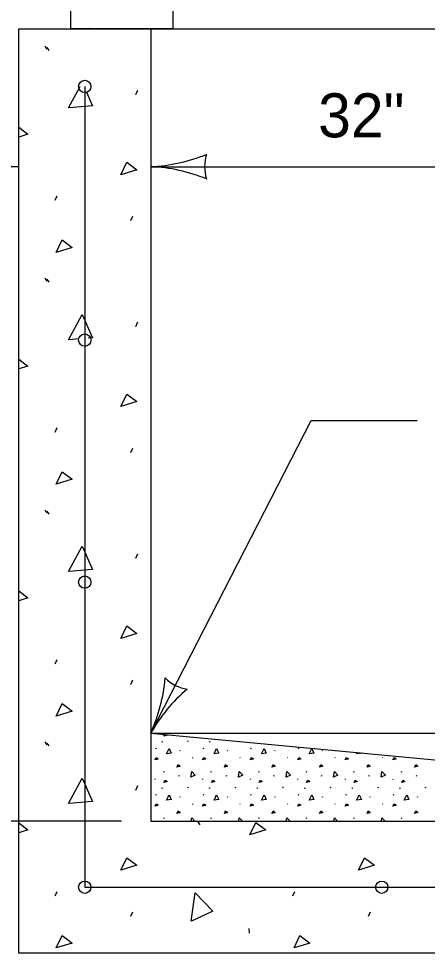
# Model space of a CAD drawing. Extents: x 49991.4 to 50041.6, y 49987.6 to 50011.4.
# Drawn here: x 50038.338 to 50038.895, y 49992.177 to 49993.451 of the extents above; entities that cross this region are included whole.
import ezdxf

# ---------------------------------------------------------------- set-up
doc = ezdxf.new("R2010")
doc.units = 0
for name, color, linetype in [('Level 1', 7, 'Continuous'), ('Level 2', 7, 'Continuous'), ('Level 3', 7, 'Continuous'), ('Level 4', 7, 'Continuous')]:
    doc.layers.add(name, color=color, linetype=linetype)

msp = doc.modelspace()

# ---------------------------------------------------------------- linework, layer by layer
at = {"layer": 'Level 1'}
for p, q in [((50038.3736, 49993.4132), (50038.3763, 49993.4092)), ((50038.3763, 49993.4117), (50038.379, 49993.4076)), ((50038.4974, 49993.3475), (50038.5001, 49993.3536)), ((50038.3878, 49993.2034), (50038.3905, 49993.2095)), ((50038.4906, 49993.1756), (50038.4933, 49993.1817)), ((50038.3736, 49993.0971), (50038.3763, 49993.0931)), ((50038.3763, 49993.0956), (50038.379, 49993.0915)), ((50038.4974, 49993.0314), (50038.5001, 49993.0375)), ((50038.3878, 49992.8873), (50038.3905, 49992.8934)), ((50038.4906, 49992.8595), (50038.4933, 49992.8656)), ((50038.3736, 49992.781), (50038.3763, 49992.777)), ((50038.3763, 49992.7795), (50038.379, 49992.7754)), ((50038.4974, 49992.7153), (50038.5001, 49992.7214)), ((50038.3878, 49992.5712), (50038.3905, 49992.5773)), ((50038.4906, 49992.5434), (50038.4933, 49992.5495)), ((50038.5179, 49992.4768), (50039.4779, 49992.3868)), ((50038.3736, 49992.465), (50038.3763, 49992.4609)), ((50038.3763, 49992.4634), (50038.379, 49992.4594)), ((50038.4974, 49992.3992), (50038.5001, 49992.4053)), ((50038.582, 49992.3559), (50038.5847, 49992.3519)), ((50038.3878, 49992.2551), (50038.3905, 49992.2612)), ((50038.7119, 49992.2551), (50038.7146, 49992.2612)), ((50038.4906, 49992.2274), (50038.4933, 49992.2335)), ((50038.8148, 49992.2274), (50038.8175, 49992.2335)), ((50038.6515, 49992.2104), (50038.6522, 49992.2043))]:
    msp.add_line(p, q, dxfattribs=at)
msp.add_lwpolyline([(50038.4091, 49993.4368), (50038.4091, 49993.6168), (50038.5479, 49993.6168), (50038.5479, 49993.4368)], close=True, dxfattribs=at)
for points in [[(50039.6579, 49992.3552), (50039.6579, 49992.1768), (50038.3379, 49992.1768), (50038.3379, 49993.4368), (50039.6579, 49993.4368), (50039.6579, 49992.5964)], [(50038.432, 49993.4368), (50038.4326, 49993.438), (50038.4342, 49993.4368)], [(50038.5179, 49993.4368), (50038.5179, 49992.3568), (50039.4779, 49992.3568), (50039.4779, 49993.4368)], [(50038.406, 49993.3292), (50038.4215, 49993.3584)], [(50038.4279, 49993.3585), (50038.4279, 49992.2668), (50039.5679, 49992.2668), (50039.5679, 49992.3563)], [(50038.4297, 49993.3516), (50038.4385, 49993.3319), (50038.4067, 49993.3292)], [(50038.3379, 49993.3029), (50038.3505, 49993.2934), (50038.3379, 49993.2894)], [(50038.4772, 49993.2382), (50038.4853, 49993.2551), (50038.4989, 49993.245), (50038.4772, 49993.2382)], [(50038.3891, 49993.1323), (50038.3972, 49993.1492), (50038.4108, 49993.1391), (50038.3891, 49993.1323)], [(50038.406, 49993.0131), (50038.4243, 49993.0477), (50038.4385, 49993.0159), (50038.4325, 49993.0153)], [(50038.4202, 49993.0143), (50038.4067, 49993.0131)], [(50038.3379, 49992.9868), (50038.3505, 49992.9773), (50038.3379, 49992.9733)], [(50038.4772, 49992.9221), (50038.4853, 49992.9391), (50038.4989, 49992.9289), (50038.4772, 49992.9221)], [(50038.3891, 49992.8162), (50038.3972, 49992.8331), (50038.4108, 49992.823), (50038.3891, 49992.8162)], [(50038.406, 49992.6971), (50038.4243, 49992.7316), (50038.4385, 49992.6998), (50038.4067, 49992.6971)], [(50038.3379, 49992.6707), (50038.3505, 49992.6612), (50038.3379, 49992.6572)], [(50038.4772, 49992.6061), (50038.4853, 49992.623), (50038.4989, 49992.6128), (50038.4772, 49992.6061)], [(50038.3891, 49992.5001), (50038.3972, 49992.5171), (50038.4108, 49992.5069), (50038.3891, 49992.5001)], [(50038.406, 49992.381), (50038.4243, 49992.4155), (50038.4385, 49992.3837), (50038.4067, 49992.381)], [(50038.3379, 49992.3546), (50038.3505, 49992.3451), (50038.3379, 49992.3411)], [(50038.653, 49992.3383), (50038.6611, 49992.3553), (50038.6747, 49992.3451), (50038.653, 49992.3383)], [(50038.4772, 49992.29), (50038.4853, 49992.3069), (50038.4989, 49992.2967), (50038.4772, 49992.29)], [(50038.8014, 49992.29), (50038.8095, 49992.3069), (50038.823, 49992.2967), (50038.8014, 49992.29)], [(50038.5729, 49992.2204), (50038.5783, 49992.259), (50038.6025, 49992.234), (50038.5736, 49992.2206)], [(50038.3891, 49992.1841), (50038.3972, 49992.201), (50038.4108, 49992.1908), (50038.3891, 49992.1841)], [(50038.7133, 49992.1841), (50038.7214, 49992.201), (50038.7349, 49992.1908), (50038.7133, 49992.1841)]]:
    msp.add_lwpolyline(points, dxfattribs=at)
for centre in [(50038.4279, 49993.3585), (50038.4279, 49993.0128), (50038.4279, 49992.6828), (50038.4279, 49992.2668), (50038.4279, 49992.2668), (50038.8329, 49992.2668)]:
    msp.add_circle(centre, 0.0084, dxfattribs=at)
at = {"layer": 'Level 3'}
for p, q in [((50038.3379, 49993.2491), (50038.1703, 49993.2491)), ((50038.5179, 49993.2491), (50039.4779, 49993.2491)), ((50038.5179, 49992.4768), (50038.7369, 49992.9029)), ((50038.7369, 49992.9029), (50038.8814, 49992.9029)), ((50038.5179, 49992.4768), (50039.0659, 49992.4768)), ((50038.4779, 49992.3568), (50037.6495, 49992.3568))]:
    msp.add_line(p, q, dxfattribs=at)
for centre, radius, start, end in [((50038.347, 49993.4713), 0.2223, 247.456, 267.6395), ((50038.5064, 49993.4818), 0.233, 272.8273, 292.0772), ((50038.6461, 49993.2491), 0.0548, 162.1388, 197.8612), ((50038.5087, 49993.027), 0.2223, 67.456, 87.6395), ((50038.3056, 49992.5729), 0.233, 335.6257, 354.8756), ((50038.3056, 49992.5729), 0.233, 335.6257, 354.8756), ((50038.5765, 49992.5908), 0.0548, 224.9372, 260.6596), ((50038.5765, 49992.5908), 0.0548, 224.9372, 260.6596), ((50038.7112, 49992.3671), 0.2223, 130.2544, 150.4379), ((50038.7112, 49992.3671), 0.2223, 130.2544, 150.4379)]:
    msp.add_arc(centre, radius, start, end, dxfattribs=at)
at = {"layer": 'Level 4'}
for p, q in [((50038.5328, 49992.4657), (50038.5334, 49992.4649)), ((50038.5334, 49992.4654), (50038.5339, 49992.4646)), ((50038.5686, 49992.4657), (50038.5691, 49992.467)), ((50038.5977, 49992.4657), (50038.5982, 49992.4649)), ((50038.5982, 49992.4654), (50038.5987, 49992.4646)), ((50038.6334, 49992.4657), (50038.6335, 49992.4659)), ((50038.5249, 49992.4557), (50038.5254, 49992.4569)), ((50038.5576, 49992.4526), (50038.5581, 49992.4538)), ((50038.5897, 49992.4557), (50038.5902, 49992.4569)), ((50038.6224, 49992.4526), (50038.623, 49992.4538)), ((50038.6545, 49992.4557), (50038.655, 49992.4569)), ((50038.6873, 49992.4526), (50038.6878, 49992.4538)), ((50038.7193, 49992.4557), (50038.7199, 49992.4569)), ((50038.7521, 49992.4526), (50038.7526, 49992.4538)), ((50038.5745, 49992.4439), (50038.5751, 49992.4431)), ((50038.6393, 49992.4439), (50038.6399, 49992.4431)), ((50038.7042, 49992.4439), (50038.7047, 49992.4431)), ((50038.769, 49992.4439), (50038.7695, 49992.4431)), ((50038.8338, 49992.4439), (50038.8344, 49992.4431)), ((50038.5236, 49992.4148), (50038.5237, 49992.4136)), ((50038.5357, 49992.4238), (50038.5362, 49992.425)), ((50038.5563, 49992.4182), (50038.5568, 49992.4194)), ((50038.5884, 49992.4148), (50038.5886, 49992.4136)), ((50038.6005, 49992.4238), (50038.601, 49992.425)), ((50038.6211, 49992.4182), (50038.6216, 49992.4194)), ((50038.6533, 49992.4148), (50038.6534, 49992.4136)), ((50038.6653, 49992.4238), (50038.6659, 49992.425)), ((50038.6859, 49992.4182), (50038.6864, 49992.4194)), ((50038.7181, 49992.4148), (50038.7182, 49992.4136)), ((50038.7302, 49992.4238), (50038.7307, 49992.425)), ((50038.7507, 49992.4182), (50038.7513, 49992.4194)), ((50038.7829, 49992.4148), (50038.783, 49992.4136)), ((50038.795, 49992.4238), (50038.7955, 49992.425)), ((50038.8156, 49992.4182), (50038.8161, 49992.4194)), ((50038.8477, 49992.4148), (50038.8479, 49992.4136)), ((50038.8598, 49992.4238), (50038.8604, 49992.425)), ((50038.8804, 49992.4182), (50038.8809, 49992.4194)), ((50038.5328, 49992.4025), (50038.5334, 49992.4017)), ((50038.5334, 49992.4022), (50038.5339, 49992.4014)), ((50038.5686, 49992.4025), (50038.5691, 49992.4037)), ((50038.5977, 49992.4025), (50038.5982, 49992.4017)), ((50038.5982, 49992.4022), (50038.5987, 49992.4014)), ((50038.6334, 49992.4025), (50038.6339, 49992.4037)), ((50038.6625, 49992.4025), (50038.663, 49992.4017)), ((50038.663, 49992.4022), (50038.6636, 49992.4014)), ((50038.6982, 49992.4025), (50038.6988, 49992.4037)), ((50038.7273, 49992.4025), (50038.7279, 49992.4017)), ((50038.7279, 49992.4022), (50038.7284, 49992.4014)), ((50038.763, 49992.4025), (50038.7636, 49992.4037)), ((50038.7921, 49992.4025), (50038.7927, 49992.4017)), ((50038.7927, 49992.4022), (50038.7932, 49992.4014)), ((50038.8279, 49992.4025), (50038.8284, 49992.4037)), ((50038.857, 49992.4025), (50038.8575, 49992.4017)), ((50038.8575, 49992.4022), (50038.8581, 49992.4014)), ((50038.8927, 49992.4025), (50038.8932, 49992.4037)), ((50038.5249, 49992.3925), (50038.5254, 49992.3937)), ((50038.5576, 49992.3894), (50038.5581, 49992.3906)), ((50038.5897, 49992.3925), (50038.5902, 49992.3937)), ((50038.6224, 49992.3894), (50038.623, 49992.3906)), ((50038.6545, 49992.3925), (50038.655, 49992.3937)), ((50038.6873, 49992.3894), (50038.6878, 49992.3906)), ((50038.7193, 49992.3925), (50038.7199, 49992.3937)), ((50038.7521, 49992.3894), (50038.7526, 49992.3906)), ((50038.7842, 49992.3925), (50038.7847, 49992.3937)), ((50038.8169, 49992.3894), (50038.8175, 49992.3906)), ((50038.849, 49992.3925), (50038.8495, 49992.3937)), ((50038.8817, 49992.3894), (50038.8823, 49992.3906)), ((50038.5745, 49992.3807), (50038.5751, 49992.3799)), ((50038.6393, 49992.3807), (50038.6399, 49992.3799)), ((50038.7042, 49992.3807), (50038.7047, 49992.3799)), ((50038.769, 49992.3807), (50038.7695, 49992.3799)), ((50038.8338, 49992.3807), (50038.8344, 49992.3799)), ((50038.5357, 49992.3605), (50038.5362, 49992.3618)), ((50038.6005, 49992.3605), (50038.601, 49992.3618)), ((50038.6653, 49992.3605), (50038.6659, 49992.3618)), ((50038.7302, 49992.3605), (50038.7307, 49992.3618)), ((50038.795, 49992.3605), (50038.7955, 49992.3618)), ((50038.8598, 49992.3605), (50038.8604, 49992.3618))]:
    msp.add_line(p, q, dxfattribs=at)
for points in [[(50038.536, 49992.4728), (50038.537, 49992.475)], [(50038.5395, 49992.4747), (50038.5403, 49992.4741), (50038.536, 49992.4728)], [(50038.5393, 49992.4489), (50038.543, 49992.4558), (50038.5458, 49992.4495), (50038.5395, 49992.4489)], [(50038.6042, 49992.4489), (50038.6078, 49992.4558), (50038.6107, 49992.4495), (50038.6043, 49992.4489)], [(50038.669, 49992.4489), (50038.6726, 49992.4558), (50038.6755, 49992.4495), (50038.6691, 49992.4489)], [(50038.7338, 49992.4489), (50038.7375, 49992.4558), (50038.7403, 49992.4495), (50038.734, 49992.4489)], [(50038.5239, 49992.4404), (50038.5255, 49992.4438), (50038.5282, 49992.4418), (50038.5239, 49992.4404)], [(50038.5887, 49992.4404), (50038.5904, 49992.4438), (50038.5931, 49992.4418), (50038.5887, 49992.4404)], [(50038.6536, 49992.4404), (50038.6552, 49992.4438), (50038.6579, 49992.4418), (50038.6536, 49992.4404)], [(50038.7184, 49992.4404), (50038.72, 49992.4438), (50038.7227, 49992.4418), (50038.7184, 49992.4404)], [(50038.7832, 49992.4404), (50038.7848, 49992.4438), (50038.7875, 49992.4418), (50038.7832, 49992.4404)], [(50038.7986, 49992.4489), (50038.7994, 49992.4504)], [(50038.805, 49992.4498), (50038.8051, 49992.4495), (50038.7988, 49992.4489)], [(50038.848, 49992.4404), (50038.8497, 49992.4438), (50038.8524, 49992.4418), (50038.848, 49992.4404)], [(50038.5536, 49992.4307), (50038.5552, 49992.4341), (50038.5579, 49992.4321), (50038.5536, 49992.4307)], [(50038.6184, 49992.4307), (50038.62, 49992.4341), (50038.6227, 49992.4321), (50038.6184, 49992.4307)], [(50038.6832, 49992.4307), (50038.6848, 49992.4341), (50038.6876, 49992.4321), (50038.6832, 49992.4307)], [(50038.7481, 49992.4307), (50038.7497, 49992.4341), (50038.7524, 49992.4321), (50038.7481, 49992.4307)], [(50038.8129, 49992.4307), (50038.8145, 49992.4341), (50038.8172, 49992.4321), (50038.8129, 49992.4307)], [(50038.8777, 49992.4307), (50038.8793, 49992.4341), (50038.882, 49992.4321), (50038.8777, 49992.4307)], [(50038.5727, 49992.4168), (50038.5738, 49992.4246), (50038.5786, 49992.4195), (50038.5728, 49992.4169)], [(50038.6375, 49992.4168), (50038.6386, 49992.4246), (50038.6435, 49992.4195), (50038.6377, 49992.4169)], [(50038.7024, 49992.4168), (50038.7034, 49992.4246), (50038.7083, 49992.4195), (50038.7025, 49992.4169)], [(50038.7672, 49992.4168), (50038.7683, 49992.4246), (50038.7731, 49992.4195), (50038.7673, 49992.4169)], [(50038.832, 49992.4168), (50038.8331, 49992.4246), (50038.8379, 49992.4195), (50038.8322, 49992.4169)], [(50038.536, 49992.4096), (50038.5376, 49992.4129), (50038.5403, 49992.4109), (50038.536, 49992.4096)], [(50038.6008, 49992.4096), (50038.6024, 49992.4129), (50038.6051, 49992.4109), (50038.6008, 49992.4096)], [(50038.6656, 49992.4096), (50038.6672, 49992.4129), (50038.6699, 49992.4109), (50038.6656, 49992.4096)], [(50038.7304, 49992.4096), (50038.7321, 49992.4129), (50038.7348, 49992.4109), (50038.7304, 49992.4096)], [(50038.7953, 49992.4096), (50038.7969, 49992.4129), (50038.7996, 49992.4109), (50038.7953, 49992.4096)], [(50038.8601, 49992.4096), (50038.8617, 49992.4129), (50038.8644, 49992.4109), (50038.8601, 49992.4096)], [(50038.5393, 49992.3857), (50038.543, 49992.3926), (50038.5458, 49992.3863), (50038.5395, 49992.3857)], [(50038.6042, 49992.3857), (50038.6078, 49992.3926), (50038.6107, 49992.3863), (50038.6043, 49992.3857)], [(50038.669, 49992.3857), (50038.6726, 49992.3926), (50038.6755, 49992.3863), (50038.6691, 49992.3857)], [(50038.7338, 49992.3857), (50038.7375, 49992.3926), (50038.7403, 49992.3863), (50038.734, 49992.3857)], [(50038.7986, 49992.3857), (50038.8023, 49992.3926), (50038.8051, 49992.3863), (50038.7988, 49992.3857)], [(50038.8635, 49992.3857), (50038.8671, 49992.3926), (50038.87, 49992.3863), (50038.8636, 49992.3857)], [(50038.5239, 49992.3772), (50038.5255, 49992.3806), (50038.5282, 49992.3785), (50038.5239, 49992.3772)], [(50038.5887, 49992.3772), (50038.5904, 49992.3806), (50038.5931, 49992.3785), (50038.5887, 49992.3772)], [(50038.6536, 49992.3772), (50038.6552, 49992.3806), (50038.6579, 49992.3785), (50038.6536, 49992.3772)], [(50038.7184, 49992.3772), (50038.72, 49992.3806), (50038.7227, 49992.3785), (50038.7184, 49992.3772)], [(50038.7832, 49992.3772), (50038.7848, 49992.3806), (50038.7875, 49992.3785), (50038.7832, 49992.3772)], [(50038.848, 49992.3772), (50038.8497, 49992.3806), (50038.8524, 49992.3785), (50038.848, 49992.3772)], [(50038.5536, 49992.3675), (50038.5552, 49992.3709), (50038.5579, 49992.3689), (50038.5536, 49992.3675)], [(50038.6184, 49992.3675), (50038.62, 49992.3709), (50038.6227, 49992.3689), (50038.6184, 49992.3675)], [(50038.6832, 49992.3675), (50038.6848, 49992.3709), (50038.6876, 49992.3689), (50038.6832, 49992.3675)], [(50038.7481, 49992.3675), (50038.7497, 49992.3709), (50038.7524, 49992.3689), (50038.7481, 49992.3675)], [(50038.8129, 49992.3675), (50038.8145, 49992.3709), (50038.8172, 49992.3689), (50038.8129, 49992.3675)], [(50038.8777, 49992.3675), (50038.8793, 49992.3709), (50038.882, 49992.3689), (50038.8777, 49992.3675)], [(50038.5732, 49992.3568), (50038.5738, 49992.3613), (50038.5782, 49992.3568)], [(50038.638, 49992.3568), (50038.6386, 49992.3613), (50038.643, 49992.3568)], [(50038.7028, 49992.3568), (50038.7034, 49992.3613), (50038.7079, 49992.3568)], [(50038.7676, 49992.3568), (50038.7683, 49992.3613), (50038.7727, 49992.3568)], [(50038.8325, 49992.3568), (50038.8331, 49992.3613), (50038.8375, 49992.3568)]]:
    msp.add_lwpolyline(points, dxfattribs=at)

# ---------------------------------------------------------------- texts
at = {"layer": 'Level 2'}
msp.add_text('32" ', height=0.06, rotation=360, dxfattribs=at).set_placement((50038.7462, 49993.2891))

doc.saveas('drawing.dxf')
